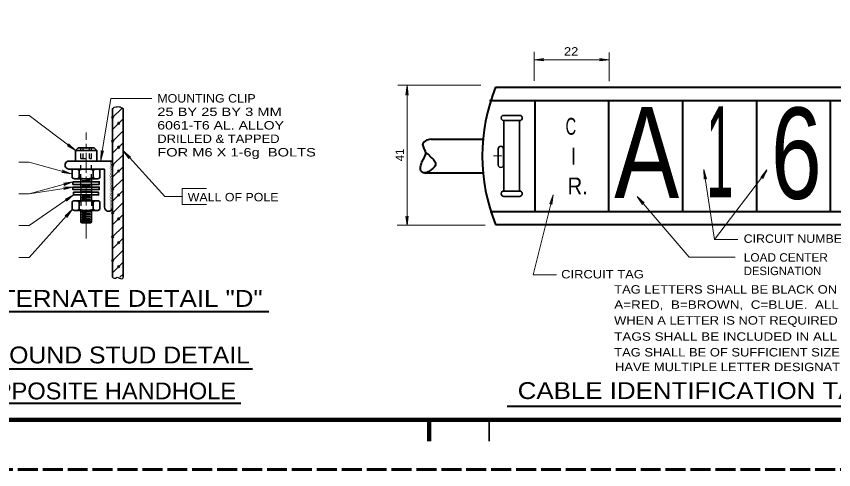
# Model space of a CAD drawing. Extents: x 312583 to 312854, y 144418 to 144597.
# Drawn here: x 312690.1 to 312763.9, y 144418.6 to 144459.5 of the extents above; entities that cross this region are included whole.
import ezdxf
from ezdxf.enums import TextEntityAlignment as Align

# ---------------------------------------------------------------- set-up
doc = ezdxf.new("R2010")
doc.units = 0
doc.header["$LTSCALE"] = 0.3
doc.header["$PDMODE"] = 32
doc.header["$PDSIZE"] = 0.15
for name, pattern in [('LONG_DASH_SHORT_DASH', [9.9, 6, -1.2, 1.5, -1.2]), ('LONG_DASHED', [7.5, 6, -1.5]), ('SHORT_DASHED', [2.7, 1.5, -1.2])]:
    doc.linetypes.add(name, pattern=pattern)
doc.layers.add('1', color=7, linetype='Continuous', lineweight=35)
doc.layers.add('2', color=7, linetype='Continuous')

msp = doc.modelspace()

# ---------------------------------------------------------------- linework, layer by layer
at = {"layer": '1', "lineweight": 13}
for p, q in [((312736.8414, 144453.6963), (312736.8414, 144456.3041)), ((312743.6048, 144453.6505), (312743.6048, 144456.2507)), ((312736.849, 144455.5873), (312737.7106, 144455.6941)), ((312736.849, 144455.5873), (312743.5971, 144455.5873)), ((312736.849, 144455.5873), (312737.7106, 144455.4805)), ((312737.7106, 144455.6941), (312737.4361, 144455.5873)), ((312737.7106, 144455.4805), (312737.4361, 144455.5873)), ((312742.7355, 144455.6941), (312743.01, 144455.5873)), ((312743.5971, 144455.5873), (312742.7355, 144455.6941)), ((312742.7355, 144455.4805), (312743.01, 144455.5873)), ((312743.5971, 144455.5873), (312742.7355, 144455.4805)), ((312724.5118, 144453.2845), (312732.0224, 144453.2845)), ((312725.3429, 144453.2541), (312725.2361, 144452.3924)), ((312725.3429, 144440.6118), (312725.3429, 144453.2541)), ((312725.3429, 144453.2541), (312725.4496, 144452.3924)), ((312725.2361, 144452.3924), (312725.3429, 144452.6669)), ((312725.4496, 144452.3924), (312725.3429, 144452.6669)), ((312697.6597, 144446.4092), (312698.5899, 144452.0974)), ((312698.5899, 144452.0974), (312702.2957, 144452.0974)), ((312698.7424, 144450.3742), (312699.5811, 144451.1977)), ((312691.2241, 144450.5419), (312690.271, 144450.5419)), ((312691.2241, 144450.5419), (312695.4103, 144447.3852)), ((312698.7424, 144449.2914), (312699.7031, 144450.2522)), ((312698.7424, 144448.2163), (312699.7031, 144449.1694)), ((312698.7424, 144447.1412), (312699.7031, 144448.0867)), ((312694.6554, 144447.8274), (312694.9451, 144447.7436)), ((312695.4103, 144447.3852), (312694.6554, 144447.8274)), ((312694.785, 144447.9952), (312694.9451, 144447.7436)), ((312695.4103, 144447.3852), (312694.785, 144447.9952)), ((312697.6825, 144446.5312), (312697.713, 144447.4004)), ((312697.6825, 144446.5312), (312697.9265, 144447.3623)), ((312697.713, 144447.4004), (312697.7817, 144447.1107)), ((312697.9265, 144447.3623), (312697.7817, 144447.1107)), ((312699.7031, 144447.3699), (312700.2064, 144446.6684)), ((312699.7031, 144447.3699), (312700.3741, 144446.8057)), ((312698.7424, 144446.0584), (312699.7031, 144447.0192)), ((312700.2064, 144446.6684), (312700.0997, 144446.9429)), ((312700.3741, 144446.8057), (312700.0997, 144446.9429)), ((312733.921, 144446.9177), (312733.1585, 144446.9177)), ((312691.2241, 144446.3482), (312690.271, 144446.3482)), ((312691.2241, 144446.3482), (312695.0214, 144445.2807)), ((312698.7424, 144444.9757), (312699.7031, 144445.9364)), ((312694.1674, 144445.4103), (312694.4571, 144445.4408)), ((312695.0214, 144445.2807), (312694.1674, 144445.4103)), ((312694.2284, 144445.6162), (312694.4571, 144445.4408)), ((312695.0214, 144445.2807), (312694.2284, 144445.6162)), ((312752.1448, 144445.6672), (312752.1752, 144444.7979)), ((312752.1448, 144445.6672), (312752.3811, 144444.8361)), ((312753.1284, 144439.3765), (312752.1448, 144445.6672)), ((312752.1752, 144444.7979), (312752.2362, 144445.0877)), ((312752.3811, 144444.8361), (312752.2362, 144445.0877)), ((312753.1284, 144439.3765), (312757.8482, 144445.5757)), ((312757.8559, 144445.6443), (312757.3069, 144444.9733)), ((312757.3069, 144444.9733), (312757.5204, 144445.1487)), ((312757.8559, 144445.6443), (312757.4822, 144444.8437)), ((312757.4822, 144444.8437), (312757.5204, 144445.1487)), ((312691.2241, 144443.4964), (312695.1739, 144444.5716)), ((312695.1739, 144444.5716), (312694.3199, 144444.4496)), ((312694.3199, 144444.4496), (312694.6097, 144444.419)), ((312695.1739, 144444.5716), (312694.3657, 144444.2437)), ((312694.3657, 144444.2437), (312694.6097, 144444.419)), ((312698.7424, 144443.9082), (312699.7031, 144444.8537)), ((312691.2241, 144443.4964), (312695.1739, 144444.0988)), ((312695.1739, 144444.0988), (312694.3047, 144444.0759)), ((312694.3047, 144444.0759), (312694.5944, 144444.0149)), ((312695.1739, 144444.0988), (312694.3351, 144443.8624)), ((312694.3351, 144443.8624), (312694.5944, 144444.0149)), ((312698.7424, 144442.8254), (312699.7031, 144443.7786)), ((312691.2241, 144443.4964), (312690.271, 144443.4964)), ((312691.2241, 144440.6218), (312695.2349, 144443.3897)), ((312695.2349, 144443.3897), (312694.4648, 144442.9932)), ((312694.4648, 144442.9932), (312694.7469, 144443.0542)), ((312695.2349, 144443.3897), (312694.5868, 144442.8102)), ((312694.5868, 144442.8102), (312694.7469, 144443.0542)), ((312736.7346, 144436.1741), (312738.5418, 144443.3797)), ((312738.5418, 144443.3797), (312738.2291, 144442.5714)), ((312738.5418, 144443.3797), (312738.435, 144442.5181)), ((312750.8332, 144437.7753), (312746.1286, 144443.2577)), ((312746.1286, 144443.2577), (312746.609, 144442.5333)), ((312746.1286, 144443.2577), (312746.7691, 144442.6705)), ((312698.7424, 144441.7427), (312699.7031, 144442.7034)), ((312705.0483, 144442.528), (312707.2214, 144442.528)), ((312738.2291, 144442.5714), (312738.3969, 144442.8078)), ((312738.435, 144442.5181), (312738.3969, 144442.8078)), ((312746.609, 144442.5333), (312746.5099, 144442.8154)), ((312746.7691, 144442.6705), (312746.5099, 144442.8154)), ((312691.2241, 144437.7472), (312695.1129, 144442.0629)), ((312695.1129, 144442.0629), (312694.4571, 144441.491)), ((312694.4571, 144441.491), (312694.7164, 144441.6207)), ((312695.1129, 144442.0629), (312694.6097, 144441.3462)), ((312694.6097, 144441.3462), (312694.7164, 144441.6207)), ((312698.75, 144440.6752), (312699.7031, 144441.6207)), ((312725.2361, 144441.4734), (312725.3429, 144441.1989)), ((312725.3429, 144440.6118), (312725.2361, 144441.4734)), ((312725.4496, 144441.4734), (312725.3429, 144441.1989)), ((312725.3429, 144440.6118), (312725.4496, 144441.4734)), ((312724.4508, 144440.6423), (312732.3884, 144440.6423)), ((312691.2241, 144440.6218), (312690.271, 144440.6218)), ((312698.7424, 144439.5924), (312699.7031, 144440.5456)), ((312698.7424, 144438.5097), (312699.7031, 144439.4704)), ((312753.1284, 144439.3765), (312755.2252, 144439.3765)), ((312691.2241, 144437.7472), (312690.271, 144437.7472)), ((312698.7424, 144437.4346), (312699.7031, 144438.3877)), ((312750.8332, 144437.7753), (312754.9913, 144437.7753)), ((312698.7424, 144436.3594), (312699.7031, 144437.3049)), ((312699.421, 144435.9477), (312699.7031, 144436.2298)), ((312736.7346, 144436.1741), (312738.8315, 144436.1741))]:
    msp.add_line(p, q, dxfattribs=at)
at = {"layer": '1', "lineweight": 40}
for p, q in [((312733.3339, 144453.1015), (312773.8455, 144453.1015)), ((312736.91, 144441.9004), (312736.91, 144451.9121)), ((312743.5819, 144441.9004), (312743.5819, 144451.9121)), ((312750.2538, 144441.9004), (312750.2538, 144451.9121)), ((312756.9256, 144441.9004), (312756.9256, 144451.9121)), ((312763.5975, 144441.9004), (312763.5975, 144451.9121)), ((312727.5236, 144448.4274), (312729.7044, 144448.4274)), ((312733.3339, 144440.7109), (312773.8455, 144440.7109)), ((312685.2992, 144432.8731), (312712.8571, 144432.8731)), ((312685.8118, 144427.6822), (312711.394, 144427.6822)), ((312686.4325, 144424.594), (312710.3473, 144424.594)), ((312734.3811, 144424.3068), (312777.466, 144424.3068))]:
    msp.add_line(p, q, dxfattribs=at)
at = {"layer": '1'}
for p, q in [((312698.7424, 144435.9477), (312698.7424, 144451.1977)), ((312699.7031, 144435.9477), (312699.7031, 144451.1977)), ((312734.0811, 144450.5701), (312735.5146, 144450.5701)), ((312734.0811, 144450.0973), (312735.5146, 144450.0973)), ((312695.4103, 144446.4397), (312695.4103, 144447.3852)), ((312697.0801, 144447.6292), (312697.3165, 144447.3852)), ((312733.5855, 144446.1171), (312733.5855, 144447.5505)), ((312734.0582, 144446.1171), (312734.0582, 144447.5505)), ((312698.7424, 144446.4397), (312694.8155, 144446.4397)), ((312698.0333, 144445.7229), (312694.8079, 144445.7229)), ((312695.1129, 144445.6314), (312695.1129, 144444.9147)), ((312695.3874, 144445.7229), (312696.3634, 144445.7229)), ((312695.7381, 144445.6314), (312695.7381, 144444.9147)), ((312697.3394, 144445.7229), (312696.3634, 144445.7229)), ((312696.9887, 144445.6314), (312696.9887, 144444.9147)), ((312697.6139, 144445.6314), (312697.6139, 144444.9147)), ((312698.0333, 144442.2688), (312698.0333, 144445.7229)), ((312695.3874, 144444.8308), (312696.3634, 144444.8308)), ((312695.8907, 144444.8156), (312695.8907, 144444.5792)), ((312695.8907, 144444.3352), (312695.8907, 144444.1064)), ((312697.3394, 144444.8308), (312696.3634, 144444.8308)), ((312696.8361, 144444.8156), (312696.8361, 144444.5792)), ((312696.8361, 144444.3352), (312696.8361, 144444.1064)), ((312695.8907, 144443.8624), (312695.8907, 144443.626)), ((312696.8361, 144443.8624), (312696.8361, 144443.626)), ((312734.0811, 144443.7381), (312735.5146, 144443.7381)), ((312695.3874, 144442.8636), (312696.3634, 144442.8636)), ((312695.8907, 144443.3897), (312695.8907, 144442.8636)), ((312697.3394, 144442.8636), (312696.3634, 144442.8636)), ((312696.8361, 144443.3897), (312696.8361, 144442.8636)), ((312734.0811, 144443.2577), (312735.5146, 144443.2577)), ((312695.1129, 144442.7797), (312695.1129, 144442.0629)), ((312695.7381, 144442.7797), (312695.7381, 144442.0629)), ((312696.9887, 144442.7797), (312696.9887, 144442.0629)), ((312697.6139, 144442.7797), (312697.6139, 144442.0629)), ((312695.3874, 144441.9714), (312696.3634, 144441.9714)), ((312695.8907, 144441.9714), (312695.8907, 144440.9497)), ((312697.3394, 144441.9714), (312696.3634, 144441.9714)), ((312696.8361, 144441.9714), (312696.8361, 144440.9497)), ((312695.8907, 144440.9497), (312696.3634, 144440.9497)), ((312696.8361, 144440.9497), (312696.3634, 144440.9497)), ((312732.75, 144423.0846), (312732.75, 144421.1646))]:
    msp.add_line(p, q, dxfattribs=at)
at = {"layer": '1', "linetype": 'LONG_DASH_SHORT_DASH', "lineweight": 13}
msp.add_line((312696.3634, 144439.4552), (312696.3634, 144449.0322), dxfattribs=at)
at = {"layer": '1', "linetype": 'SHORT_DASHED', "lineweight": 25}
for p, q in [((312695.8907, 144446.6684), (312695.8907, 144447.6292)), ((312696.0889, 144446.6684), (312696.0889, 144447.6292)), ((312696.6531, 144446.6684), (312696.6531, 144447.6292)), ((312696.8361, 144446.6684), (312696.8361, 144447.6292)), ((312695.8907, 144446.6684), (312696.8361, 144446.6684)), ((312695.8907, 144444.8156), (312695.8907, 144446.4397)), ((312696.8361, 144444.8156), (312696.8361, 144446.4397)), ((312695.8907, 144444.3352), (312695.8907, 144444.5792)), ((312696.8361, 144444.3352), (312696.8361, 144444.5792)), ((312695.8907, 144444.1064), (312695.8907, 144443.8624)), ((312695.8907, 144443.626), (312695.8907, 144443.3897)), ((312696.8361, 144444.1064), (312696.8361, 144443.8624)), ((312696.8361, 144443.626), (312696.8361, 144443.3897)), ((312695.8907, 144442.8636), (312695.8907, 144441.9714)), ((312696.8361, 144442.8636), (312696.8361, 144441.9714))]:
    msp.add_line(p, q, dxfattribs=at)
at = {"layer": '1', "lineweight": 25}
for p, q in [((312696.005, 144444.6936), (312696.3634, 144444.6936)), ((312696.7218, 144444.6936), (312696.3634, 144444.6936)), ((312696.005, 144444.2208), (312696.3634, 144444.2208)), ((312696.005, 144444.2208), (312696.7218, 144444.2208)), ((312696.005, 144443.7404), (312696.7218, 144443.7404)), ((312696.7218, 144444.2208), (312696.3634, 144444.2208)), ((312695.883, 144443.1609), (312696.3634, 144443.1609)), ((312695.883, 144442.9169), (312696.3634, 144442.9169)), ((312696.005, 144443.2677), (312696.7218, 144443.2677)), ((312696.005, 144443.0313), (312696.7218, 144443.0313)), ((312696.8438, 144443.1609), (312696.3634, 144443.1609)), ((312696.8438, 144442.9169), (312696.3634, 144442.9169)), ((312695.883, 144441.8647), (312696.3634, 144441.8647)), ((312695.883, 144441.6207), (312696.3634, 144441.6207)), ((312695.883, 144441.3843), (312696.3634, 144441.3843)), ((312696.005, 144441.7274), (312696.7218, 144441.7274)), ((312696.005, 144441.4987), (312696.7218, 144441.4987)), ((312696.8438, 144441.8647), (312696.3634, 144441.8647)), ((312696.8438, 144441.6207), (312696.3634, 144441.6207)), ((312696.8438, 144441.3843), (312696.3634, 144441.3843)), ((312695.883, 144441.1479), (312696.3634, 144441.1479)), ((312695.9974, 144441.0564), (312696.7141, 144441.0564)), ((312696.005, 144441.2699), (312696.7218, 144441.2699)), ((312696.8438, 144441.1479), (312696.3634, 144441.1479))]:
    msp.add_line(p, q, dxfattribs=at)
at = {"layer": '1', "lineweight": 158}
for p, q in [((312616.5, 144423.0846), (312849, 144423.0846)), ((312727.35, 144421.1646), (312727.35, 144423.0846))]:
    msp.add_line(p, q, dxfattribs=at)
at = {"layer": '1', "linetype": 'LONG_DASHED', "lineweight": 60}
msp.add_line((312851.75, 144418.5846), (312583.526, 144418.5846), dxfattribs=at)
at = {"layer": '1', "lineweight": 158}
msp.add_lwpolyline([(312849, 144423.0846), (312849, 144585.0846), (312616.5, 144585.0846), (312616.5, 144423.0846)], close=True, dxfattribs=at)
msp.add_lwpolyline([(312616.5, 144585.0846), (312616.5, 144423.0846), (312849, 144423.0846)], dxfattribs=at)
at = {"layer": '1', "lineweight": 40}
for points in [[(312732.8001, 144451.9121), (312756.9256, 144451.9121), (312774.1734, 144451.9121)], [(312729.7044, 144448.4274), (312730.7109, 144448.4274), (312732.2206, 144448.4274)], [(312726.9289, 144445.3774), (312729.7044, 144445.3774), (312731.0311, 144445.3774), (312732.2206, 144445.3774)], [(312732.8535, 144441.9004), (312756.9256, 144441.9004), (312774.2268, 144441.9004)]]:
    msp.add_lwpolyline(points, dxfattribs=at)
at = {"layer": '1'}
for points in [[(312734.0811, 144450.0973), (312734.0811, 144445.2707), (312734.0811, 144443.7381)], [(312735.5146, 144450.0973), (312735.5146, 144445.2707), (312735.5146, 144443.7381)], [(312697.0801, 144447.6292), (312695.6467, 144447.6292), (312695.4103, 144447.3852)], [(312697.3165, 144446.4397), (312697.3165, 144447.3852), (312695.4103, 144447.3852)], [(312695.8907, 144440.9497), (312695.9517, 144440.8658), (312696.3634, 144440.8658)], [(312696.8361, 144440.9497), (312696.7751, 144440.8658), (312696.3634, 144440.8658)]]:
    msp.add_lwpolyline(points, dxfattribs=at)
at = {"layer": '1', "lineweight": 13}
for points in [[(312699.7031, 144447.3852), (312703.4851, 144443.2524), (312705.0483, 144443.2524)], [(312705.0483, 144442.528), (312705.0483, 144443.9539), (312707.2214, 144443.9539)]]:
    msp.add_lwpolyline(points, dxfattribs=at)
at = {"layer": '1'}
for points in [[(312695.1739, 144444.5716), (312695.1739, 144444.3352), (312697.5529, 144444.3352), (312697.5529, 144444.5716)], [(312695.1739, 144444.0988), (312695.1739, 144443.8624), (312697.5529, 144443.8624), (312697.5529, 144444.0988)], [(312695.2349, 144443.626), (312695.2349, 144443.3897), (312697.4919, 144443.3897), (312697.4919, 144443.626)]]:
    msp.add_lwpolyline(points, close=True, dxfattribs=at)
at = {"layer": '1', "lineweight": 40}
msp.add_arc((312748.8727, 144446.9062), 16.7284, 158.26294, 201.73706, dxfattribs=at)
at = {"layer": '1'}
for centre, radius, start, end in [((312734.0731, 144450.3337), 0.2364, 88.05031, 270.1016), ((312735.5147, 144450.3336), 0.2364, 271.83343, 90.01466), ((312733.8219, 144447.5506), 0.2364, 1.83342, 180.01466), ((312694.8136, 144446.0794), 0.3565, 89.69361, 270.30639), ((312733.8218, 144446.109), 0.2364, 178.05031, 0.1016), ((312695.4024, 144445.2067), 0.5159, 91.66257, 124.1297), ((312695.1532, 144444.2776), 1.4773, 66.63635, 78.22986), ((312696.4292, 144443.0585), 2.6662, 91.405, 105.00202), ((312696.2985, 144443.0585), 2.6662, 74.99798, 88.595), ((312697.5745, 144444.2776), 1.4773, 101.77014, 113.36365), ((312697.3254, 144445.2067), 0.5159, 55.8703, 88.33743), ((312695.4024, 144445.3489), 0.5159, 235.8703, 268.33743), ((312695.1532, 144446.278), 1.4773, 281.77014, 293.36365), ((312696.4292, 144447.4971), 2.6662, 254.99798, 268.595), ((312696.2985, 144447.4971), 2.6662, 271.405, 285.00202), ((312697.5745, 144446.278), 1.4773, 246.63635, 258.22986), ((312697.3254, 144445.3489), 0.5159, 271.66257, 304.1297), ((312734.0849, 144443.4979), 0.2402, 90.90938, 269.09062), ((312735.5111, 144443.4979), 0.2402, 270.85072, 89.14928), ((312695.4024, 144442.3474), 0.5159, 91.66257, 124.1297), ((312695.1532, 144441.4182), 1.4773, 66.63635, 78.22986), ((312696.4292, 144440.1991), 2.6662, 91.405, 105.00202), ((312696.2985, 144440.1991), 2.6662, 74.99798, 88.595), ((312697.5745, 144441.4182), 1.4773, 101.77014, 113.36365), ((312697.3254, 144442.3474), 0.5159, 55.8703, 88.33743), ((312698.3897, 144442.2669), 0.3565, 179.69361, 0.30639), ((312695.4024, 144442.4895), 0.5159, 235.8703, 268.33743), ((312695.1532, 144443.4187), 1.4773, 281.77014, 293.36365), ((312696.4292, 144444.6377), 2.6662, 254.99798, 268.595), ((312696.2985, 144444.6377), 2.6662, 271.405, 285.00202), ((312697.5745, 144443.4187), 1.4773, 246.63635, 258.22986), ((312697.3254, 144442.4895), 0.5159, 271.66257, 304.1297)]:
    msp.add_arc(centre, radius, start, end, dxfattribs=at)
at = {"layer": '1', "lineweight": 25}
for points in [[(312698.7424, 144451.1977), (312698.9025, 144451.2968), (312699.1694, 144451.3502), (312699.3371, 144451.3502), (312699.7031, 144451.1977)], [(312698.7424, 144435.9477), (312699.0169, 144435.8714), (312699.1694, 144435.9553), (312699.3677, 144435.8714), (312699.6879, 144435.8714), (312699.7031, 144435.9477)]]:
    msp.add_spline(points, degree=3, dxfattribs=at)
at = {"layer": '1', "lineweight": 40}
msp.add_spline([(312727.5236, 144448.4274), (312726.9822, 144448.2521), (312726.7535, 144447.9165), (312726.8755, 144447.5811), (312727.0432, 144447.2227), (312727.3025, 144447.0092), (312727.516, 144446.7652), (312727.8058, 144446.5059), (312727.9125, 144446.0942), (312727.6685, 144445.7587), (312727.3482, 144445.5452), (312726.906, 144445.3698), (312726.601, 144445.5757), (312726.601, 144446.0332), (312726.723, 144446.4297), (312726.9518, 144446.8567), (312727.0738, 144447.1769)], degree=3, dxfattribs=at)
at = {"layer": '1'}
for p in [(312698.7653, 144450.3894), (312699.3067, 144449.8557), (312698.7653, 144448.2392), (312699.3067, 144447.6902), (312698.7653, 144446.0737), (312699.3067, 144445.5399), (312698.7653, 144443.9234), (312699.3067, 144443.382), (312698.7653, 144441.7656), (312699.3067, 144441.2242), (312698.7653, 144439.6077), (312699.3067, 144439.0739), (312698.7653, 144437.4498), (312699.3067, 144436.9084)]:
    msp.add_point(p, dxfattribs=at)

# ---------------------------------------------------------------- texts
for s, height, width, p in [('22 ', 0.76, 1.15, (312739.5166, 144455.9634)), ('MOUNTING CLIP', 0.76, 1.1, (312702.7913, 144451.7263)), ('25 BY 25 BY 3 MM', 0.76, 1.3, (312702.7913, 144450.5088)), ('6061-T6 AL. ALLOY', 0.76, 1.25, (312702.7913, 144449.2913)), ('DRILLED & TAPPED', 0.76, 1.15, (312702.7913, 144448.0738)), ('FOR M6 X 1-6g  BOLTS', 0.76, 1.3, (312702.7913, 144446.8563)), ('X', 0.3088, 0.65, (312698.4755, 144445.761)), ('X', 0.3088, 0.65, (312698.4831, 144446.066)), ('X', 0.3088, 0.65, (312698.4679, 144445.1282)), ('X', 0.3088, 0.65, (312698.4679, 144444.8079)), ('X', 0.3088, 0.65, (312698.4831, 144445.4408)), ('X', 0.3088, 0.65, (312698.4755, 144444.1979)), ('X', 0.3088, 0.65, (312698.4831, 144444.5029)), ('X', 0.3088, 0.65, (312698.4831, 144443.8929)), ('X', 0.305, 0.7, (312698.4831, 144443.5803)), ('X', 0.305, 0.7, (312698.4679, 144443.2677)), ('X', 0.305, 0.7, (312698.4679, 144442.9627)), ('X', 0.305, 0.7, (312698.4831, 144442.6577)), ('WALL OF POLE', 0.76, 1.1, (312705.539, 144442.8066)), ('X', 0.305, 0.7, (312698.4831, 144442.3527)), ('X', 0.305, 0.7, (312698.4908, 144442.0553)), ('CIRCUIT NUMBERS', 0.76, 1.1, (312755.7482, 144439.0616)), ('LOAD CENTER', 0.76, 1.05, (312755.7634, 144437.3649)), ('CIRCUIT TAG', 0.76, 1.15, (312739.2661, 144435.8488))]:
    msp.add_text(s, height=height, dxfattribs=dict(at, width=width)).set_placement(p)
for s, height, width, p in [('A', 8.235, 0.8, (312746.9903, 144443.0975)), ('1', 8.235, 0.4, (312753.6011, 144443.1585)), ('6', 8.235, 0.75, (312760.5056, 144443.0365)), ('C', 1.525, 0.65, (312740.143, 144448.8163)), ('I', 1.525, 0.85, (312740.3794, 144446.1247)), ('R.', 1.525, 0.9, (312740.7607, 144443.4331)), ('ALTERNATE DETAIL "D"', 1.52, 1.15, (312699.0049, 144433.2825)), ('GROUND STUD DETAIL', 1.52, 1.1, (312698.6081, 144428.1769)), ('OPPOSITE HANDHOLE', 1.52, 1.05, (312698.2257, 144424.93)), ('CABLE IDENTIFICATION TAG DETAIL', 1.52, 1.15, (312755.9257, 144424.9611))]:
    msp.add_text(s, height=height, dxfattribs=dict(at, width=width)).set_placement(p, align=Align.CENTER)
msp.add_text('41 ', height=0.76, rotation=90, dxfattribs=at).set_placement((312725.0659, 144446.4264))
msp.add_text('DESIGNATION', height=0.76, dxfattribs=at).set_placement((312755.7634, 144436.1474))
at = {"layer": '2'}
for s, width, p in [('TAG LETTERS SHALL BE BLACK ON YELLOW. THE PHASE SYMBOL SHALL BE:', 1.15, (312744.0546, 144434.4755)), ('A=RED,  B=BROWN,  C=BLUE.  ALL NEUTRAL CABLE SHALL HAVE A BLANK WHITE SPACER.', 1.2, (312744.0546, 144433.103)), ('WHEN A LETTER IS NOT REQUIRED A YELLOW SPACER SHALL BE USED.', 1.15, (312744.047, 144431.6771)), ('TAGS SHALL BE INCLUDED IN ALL CABLE ITEMS.', 1.2, (312744.047, 144430.2207)), ('TAG SHALL BE OF SUFFICIENT SIZE TO ACCOMMODATE LOAD CENTERS THAT', 1.15, (312744.0546, 144428.8025)), ('HAVE MULTIPLE LETTER DESIGNATIONS.', 1.15, (312744.1309, 144427.4757))]:
    msp.add_text(s, height=0.76, dxfattribs=dict(at, width=width)).set_placement(p)

doc.saveas('drawing.dxf')
